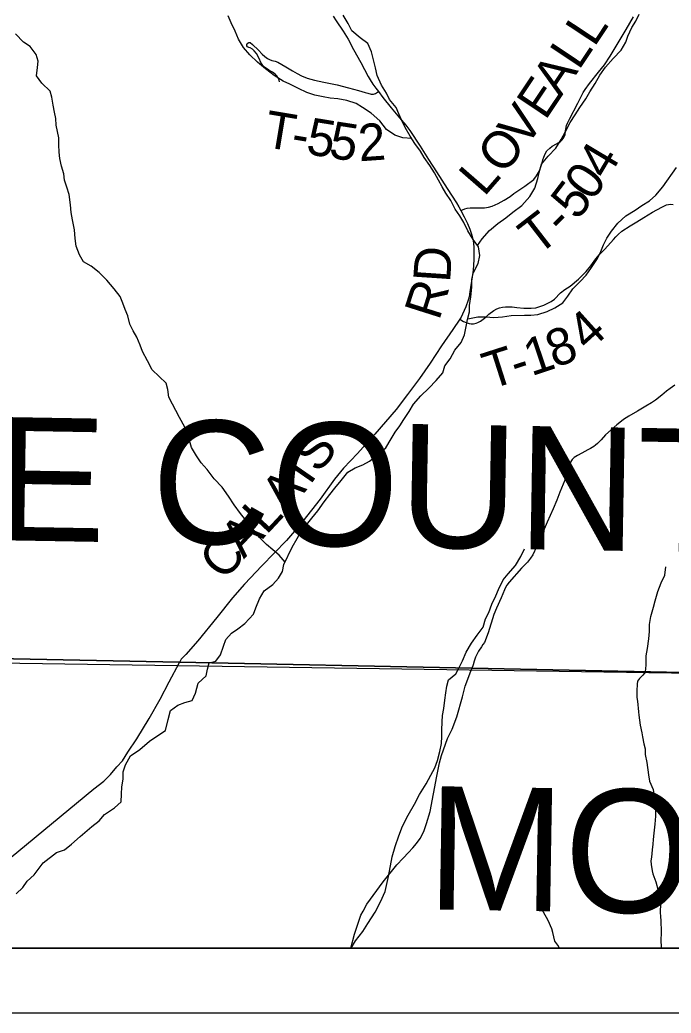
# Model space of a CAD drawing. Extents: x 0 to 34, y 0 to 22.
# Drawn here: x 25.315 to 26.315, y 14 to 15.526 of the extents above; entities that cross this region are included whole.
import ezdxf

# ---------------------------------------------------------------- set-up
doc = ezdxf.new("R2010")
doc.units = 0
for name, color, linetype in [('GM_X_Corporation', 7, 'Continuous'), ('GM_X_County', 7, 'Continuous'), ('GM_X_County_Road', 7, 'Continuous'), ('GM_X_County_Road_Text', 7, 'Continuous'), ('GM_X_County_Text', 7, 'Continuous'), ('GM_X_Minor_River', 7, 'Continuous'), ('GM_X_Township_Road', 7, 'Continuous'), ('GM_X_Township_Road_Text', 7, 'Continuous'), ('SH_Data', 7, 'Continuous')]:
    doc.layers.add(name, color=color, linetype=linetype)

msp = doc.modelspace()

# ---------------------------------------------------------------- linework, layer by layer
at = {"layer": 'GM_X_Corporation'}
msp.add_lwpolyline([(23.5167, 20.3276), (23.5167, 14.5642), (23.7464, 14.562), (24.4108, 14.5557), (24.414, 14.5556), (24.9788, 14.5503), (25.0494, 14.5496), (25.56, 14.5392), (26.009, 14.53), (26.3333, 14.5233), (26.7998, 14.5186), (27.0057, 14.5136), (27.0124, 14.988), (27.0234, 16.6611), (27.0349, 17.5522)], dxfattribs=at)
msp.add_lwpolyline([(23.5167, 20.3276), (23.5167, 14.5642), (23.7464, 14.562), (24.4108, 14.5557), (24.414, 14.5556), (24.9788, 14.5503), (25.0494, 14.5496), (25.56, 14.5392), (26.009, 14.53), (26.3333, 14.5233), (26.7998, 14.5186), (27.0057, 14.5136), (27.0124, 14.988), (27.0234, 16.6611), (27.0349, 17.5522)], dxfattribs=at)
for points in [[(23.5167, 14.5642), (23.5167, 14.1), (30.3167, 14.1), (30.3167, 14.4639), (30.3098, 14.464), (29.2367, 14.4822), (29.1713, 14.4832), (28.7853, 14.4893), (28.4032, 14.497), (27.8031, 14.5091), (27.2999, 14.5107), (27.0057, 14.5136), (26.7998, 14.5186), (26.3333, 14.5233), (26.009, 14.53), (25.56, 14.5392), (25.0494, 14.5496), (24.9788, 14.5503), (24.414, 14.5556), (24.4108, 14.5557), (23.7464, 14.562)], [(23.5167, 14.5642), (23.5167, 14.1), (27.795, 14.1), (27.8031, 14.5091), (27.2999, 14.5107), (27.0057, 14.5136), (26.7998, 14.5186), (26.3333, 14.5233), (26.009, 14.53), (25.56, 14.5392), (25.0494, 14.5496), (24.9788, 14.5503), (24.414, 14.5556), (24.4108, 14.5557), (23.7464, 14.562)]]:
    msp.add_lwpolyline(points, close=True, dxfattribs=at)
at = {"layer": 'GM_X_County'}
msp.add_line((23.5167, 14.5642), (30.3167, 14.4639), dxfattribs=at)
at = {"layer": 'GM_X_County_Road'}
for points in [[(25.7962, 15.5317), (25.801, 15.5244), (25.8113, 15.5087), (25.819, 15.4965), (25.8276, 15.4806), (25.8387, 15.4604), (25.8498, 15.4392), (25.8529, 15.4338), (25.857, 15.4273), (25.8615, 15.4212), (25.8656, 15.4158), (25.8726, 15.4068), (25.8854, 15.3909), (25.8981, 15.3755), (25.9076, 15.3642), (25.9138, 15.3559), (25.9296, 15.332), (25.9427, 15.3115), (25.9547, 15.2928), (25.9715, 15.267), (25.9857, 15.2452), (25.9895, 15.2389), (25.9925, 15.2332), (25.9975, 15.2235), (26.0024, 15.2134), (26.0061, 15.2044), (26.0089, 15.1968), (26.0108, 15.1893), (26.0116, 15.1835), (26.0124, 15.1756), (26.0123, 15.1576), (26.0113, 15.1416), (26.0098, 15.1315), (26.0064, 15.1084), (26.005, 15.1006), (26.0038, 15.0954), (26, 15.0851), (25.9948, 15.0737), (25.9926, 15.0694), (25.9908, 15.0663), (25.9798, 15.0502), (25.9626, 15.0255), (25.9451, 14.9988), (25.9286, 14.975), (25.9106, 14.9503), (25.893, 14.9275), (25.8603, 14.8896), (25.8336, 14.86), (25.8119, 14.8371), (25.7981, 14.8206), (25.7763, 14.7897), (25.7498, 14.756), (25.7401, 14.744), (25.7245, 14.7262), (25.6868, 14.6873), (25.66, 14.6589), (25.6414, 14.6379), (25.6172, 14.6077), (25.5882, 14.572), (25.5699, 14.5508), (25.5624, 14.5439), (25.5602, 14.5386)], [(25.2092, 14.1), (25.2296, 14.1618), (25.2313, 14.1687), (25.2327, 14.1725), (25.2342, 14.1752), (25.2363, 14.1795), (25.2381, 14.1826), (25.2403, 14.1864), (25.2443, 14.1911), (25.2476, 14.1954), (25.4286, 14.3447), (25.4438, 14.3563), (25.4541, 14.3664), (25.4637, 14.3782), (25.4725, 14.3877), (25.4808, 14.4011), (25.4947, 14.4212), (25.5133, 14.4528), (25.5302, 14.4822), (25.544, 14.509), (25.5602, 14.5386)]]:
    msp.add_lwpolyline(points, dxfattribs=at)
at = {"layer": 'GM_X_Minor_River'}
for points in [[(25.9169, 15.3437), (25.9034, 15.3446), (25.8909, 15.3491), (25.878, 15.3574), (25.8677, 15.371), (25.8548, 15.3827), (25.8415, 15.3914), (25.8316, 15.3978), (25.8172, 15.4024), (25.8035, 15.4046), (25.7917, 15.4057), (25.7807, 15.4079), (25.7682, 15.4105), (25.7557, 15.4147), (25.7428, 15.4207), (25.7298, 15.4271), (25.7192, 15.432), (25.7055, 15.4407), (25.6922, 15.4509), (25.6801, 15.4611), (25.6679, 15.4725), (25.6584, 15.4838), (25.6508, 15.4967), (25.6458, 15.5088), (25.6393, 15.5217), (25.6347, 15.5323)], [(25.968, 14.9944), (25.9759, 15.0051), (25.9831, 15.0184), (25.9929, 15.0302), (25.9978, 15.042), (26.0004, 15.0552), (26.0027, 15.0655), (26.0057, 15.0777), (26.0057, 15.0871), (26.0079, 15.1004), (26.009, 15.1152), (26.009, 15.1278), (26.012, 15.1377), (26.0192, 15.1517), (26.0215, 15.1639), (26.0195, 15.1772), (26.0115, 15.1889), (26.0032, 15.2022), (25.9967, 15.2147), (25.991, 15.2249), (25.9834, 15.2355), (25.9769, 15.2484), (25.9693, 15.2597), (25.9639, 15.2696), (25.9582, 15.2798), (25.9517, 15.2912), (25.9449, 15.3022), (25.9358, 15.3147), (25.9304, 15.3245), (25.9217, 15.3363), (25.9144, 15.3476), (25.9068, 15.3605), (25.9011, 15.3723), (25.8973, 15.3817), (25.8931, 15.3912), (25.8828, 15.4037), (25.8779, 15.4136), (25.8702, 15.4257), (25.8638, 15.4405), (25.8611, 15.4522), (25.858, 15.4647), (25.8553, 15.4769), (25.8496, 15.4898), (25.8378, 15.4985), (25.8249, 15.509), (25.8192, 15.5204), (25.8116, 15.5333)], [(26.0179, 15.1796), (26.0252, 15.1897), (26.0365, 15.2026), (26.049, 15.2133), (26.0616, 15.2221), (26.0722, 15.2305), (26.0858, 15.2411), (26.0983, 15.2545), (26.1062, 15.2674), (26.1104, 15.2822), (26.1126, 15.2917), (26.1164, 15.3042), (26.1266, 15.3168), (26.1383, 15.329), (26.1467, 15.3423), (26.1531, 15.3548), (26.1603, 15.3682), (26.1682, 15.3803), (26.1754, 15.3917), (26.1845, 15.405), (26.1905, 15.4153), (26.1985, 15.4282), (26.206, 15.4412), (26.2147, 15.4533), (26.2265, 15.4667), (26.2389, 15.4796), (26.2458, 15.4918), (26.2488, 15.5013), (26.2552, 15.5146), (26.2612, 15.5241), (26.2661, 15.5347)], [(25.5183, 14.9885), (25.5111, 15.0024), (25.5034, 15.0168), (25.4996, 15.0263), (25.4943, 15.0388), (25.489, 15.0483), (25.484, 15.0585), (25.4806, 15.0714), (25.4767, 15.0809), (25.4729, 15.0908), (25.4687, 15.101), (25.4596, 15.1131), (25.4482, 15.1264), (25.4368, 15.1377), (25.4242, 15.1479), (25.4125, 15.1543), (25.4064, 15.1649), (25.4014, 15.1782), (25.3999, 15.19), (25.3987, 15.2033), (25.3956, 15.2188), (25.3937, 15.2302), (25.3925, 15.2419), (25.3906, 15.2579), (25.3872, 15.2693), (25.3833, 15.2799), (25.3822, 15.2894), (25.3787, 15.3015), (25.3761, 15.3133), (25.3753, 15.3227), (25.3745, 15.3341), (25.3745, 15.3448), (25.3726, 15.3546), (25.3706, 15.3641), (25.3702, 15.3744), (25.3679, 15.3842), (25.366, 15.3948), (25.3637, 15.4074), (25.3614, 15.4168), (25.3485, 15.4286), (25.3405, 15.4403), (25.342, 15.4528), (25.3427, 15.4627), (25.3397, 15.4729), (25.3305, 15.4854), (25.3206, 15.4919), (25.3081, 15.5047)], [(26.0029, 15.0665), (26.0186, 15.0697), (26.0308, 15.0698), (26.0429, 15.069), (26.0562, 15.0698), (26.0698, 15.0718), (26.0903, 15.0726), (26.0998, 15.0726), (26.1104, 15.0734), (26.1252, 15.078), (26.1366, 15.0838), (26.1491, 15.0914), (26.1567, 15.1017), (26.1646, 15.1131), (26.1756, 15.1241), (26.1847, 15.134), (26.1923, 15.1439), (26.2013, 15.158), (26.2066, 15.1675), (26.2115, 15.1804), (26.2164, 15.1907), (26.224, 15.2013), (26.2335, 15.2135), (26.2456, 15.2249), (26.2604, 15.2337), (26.2706, 15.241), (26.282, 15.2478), (26.2918, 15.257), (26.3028, 15.2695), (26.3237, 15.2992)], [(25.7222, 14.6928), (25.7133, 14.7037), (25.7034, 14.712), (25.6939, 14.7199), (25.6828, 14.7309), (25.6744, 14.7422), (25.6657, 14.7528), (25.6538, 14.7675), (25.6443, 14.7811), (25.6355, 14.7943), (25.6256, 14.8079), (25.6134, 14.8207), (25.6027, 14.8355), (25.5932, 14.8456), (25.586, 14.8562), (25.5783, 14.8691), (25.5737, 14.885), (25.5683, 14.9005), (25.5599, 14.9152), (25.5545, 14.9258), (25.5492, 14.9357), (25.5438, 14.9463), (25.5422, 14.958), (25.5395, 14.9679), (25.5183, 14.9885)], [(25.6058, 14.538), (25.6158, 14.5408), (25.6229, 14.5507), (25.6278, 14.564), (25.6315, 14.5739), (25.6398, 14.5838), (25.6496, 14.5903), (25.6605, 14.5987), (25.6737, 14.6128), (25.6774, 14.6227), (25.683, 14.6368), (25.6901, 14.6486), (25.7033, 14.6585), (25.7123, 14.6681), (25.7183, 14.6783), (25.7205, 14.6894), (25.7333, 14.716), (25.7407, 14.7293), (25.7471, 14.7403), (25.7554, 14.7503), (25.7633, 14.7605), (25.7727, 14.772), (25.7824, 14.7857), (25.7911, 14.7971), (25.7986, 14.8066), (25.8084, 14.8185), (25.8185, 14.8314), (25.8298, 14.8379), (25.8419, 14.8426), (25.8521, 14.8479), (25.8668, 14.8598), (25.877, 14.8686), (25.8852, 14.8826), (25.8916, 14.8925), (25.8987, 14.9021), (25.9047, 14.912), (25.913, 14.9242), (25.9197, 14.9356), (25.931, 14.9482), (25.9434, 14.96), (25.9543, 14.9718), (25.9645, 14.9836), (25.968, 14.9944)], [(25.9895, 14.5301), (25.995, 14.5415), (26.0006, 14.5548), (26.0089, 14.5682), (26.0172, 14.5807), (26.0265, 14.5929), (26.0303, 14.6058), (26.0351, 14.6157), (26.04, 14.6283), (26.0463, 14.6412), (26.0501, 14.6511), (26.0575, 14.6655), (26.0651, 14.6751), (26.0763, 14.688), (26.0846, 14.7014), (26.0902, 14.7132)], [(26.2761, 14.5242), (26.2771, 14.5348), (26.277, 14.5492), (26.2792, 14.5603), (26.2814, 14.5751), (26.2824, 14.5865), (26.2824, 14.5971), (26.2842, 14.6096), (26.2883, 14.624), (26.2909, 14.6335), (26.295, 14.648), (26.3002, 14.6609), (26.3058, 14.6727), (26.3072, 14.6856)], [(25.3091, 14.1831), (25.3192, 14.1931), (25.3262, 14.203), (25.3367, 14.2127), (25.3504, 14.2311), (25.371, 14.247), (25.3834, 14.251), (25.3943, 14.2595), (25.4077, 14.2714), (25.4253, 14.2865), (25.4369, 14.2954), (25.4451, 14.3054), (25.4604, 14.3155), (25.4705, 14.3248), (25.4711, 14.3365), (25.4717, 14.3476), (25.4734, 14.3594), (25.4736, 14.3708), (25.4773, 14.3815), (25.4846, 14.3952), (25.4992, 14.4053), (25.5142, 14.4177), (25.5269, 14.4266), (25.5386, 14.4344), (25.5425, 14.4512), (25.5464, 14.4649), (25.5573, 14.4734), (25.5682, 14.4773), (25.5795, 14.4802), (25.5847, 14.4916), (25.589, 14.5069), (25.6013, 14.5181), (25.603, 14.5284), (25.6058, 14.538)], [(25.8236, 14.1), (25.8305, 14.1113), (25.8417, 14.1255), (25.8494, 14.1378), (25.8609, 14.155), (25.869, 14.1711), (25.876, 14.1868), (25.8813, 14.2097), (25.8866, 14.2401), (25.8912, 14.2558), (25.8971, 14.2722), (25.9029, 14.2871), (25.9114, 14.3043), (25.9213, 14.3212), (25.9287, 14.3357), (25.939, 14.3522), (25.9464, 14.3656), (25.9523, 14.3771), (25.9567, 14.3882), (25.9603, 14.4019), (25.9627, 14.4141), (25.963, 14.4251), (25.9632, 14.435), (25.9638, 14.4475), (25.9644, 14.4574), (25.9661, 14.4681), (25.9678, 14.481), (25.9695, 14.4921), (25.9709, 14.5023), (25.9734, 14.5123), (25.9848, 14.5214), (25.9895, 14.5301)], [(26.2761, 14.5242), (26.272, 14.5194), (26.2668, 14.5142), (26.2637, 14.5102), (26.2634, 14.5053), (26.2628, 14.495), (26.263, 14.4848), (26.2638, 14.4791), (26.2655, 14.4631), (26.266, 14.4578), (26.2677, 14.4423), (26.2702, 14.4309), (26.2714, 14.4245), (26.2735, 14.4139), (26.2755, 14.4059), (26.2756, 14.3972), (26.278, 14.385), (26.2806, 14.3661), (26.2822, 14.3562), (26.2877, 14.3438), (26.2915, 14.3203), (26.2914, 14.3024), (26.2904, 14.2902), (26.2887, 14.2765), (26.2877, 14.2666), (26.2874, 14.2598), (26.2864, 14.2507), (26.2851, 14.2396), (26.2844, 14.2339), (26.2849, 14.2282), (26.2861, 14.2187), (26.2874, 14.2138), (26.2921, 14.2017), (26.2953, 14.1885), (26.2977, 14.1767), (26.299, 14.1684), (26.2988, 14.1547), (26.2993, 14.1486), (26.2998, 14.1418), (26.3, 14.1254), (26.2995, 14.1102), (26.2999, 14.1034), (26.3, 14.1)], [(26.1439, 14.1), (26.1413, 14.1042), (26.1367, 14.1106), (26.1339, 14.1239), (26.1319, 14.1296), (26.1264, 14.1424), (26.1194, 14.1552), (26.1148, 14.1631), (26.1127, 14.173), (26.1119, 14.1787), (26.111, 14.1897), (26.1105, 14.1965), (26.1107, 14.211), (26.1104, 14.2273), (26.1115, 14.2338), (26.1128, 14.2467), (26.1145, 14.2589), (26.1159, 14.2665), (26.1151, 14.2718), (26.1148, 14.287), (26.114, 14.2927), (26.1113, 14.2987)]]:
    msp.add_lwpolyline(points, dxfattribs=at)
at = {"layer": 'GM_X_Township_Road'}
for points in [[(26.1719, 15.398), (26.1803, 15.4143), (26.1834, 15.4193), (26.19, 15.4281), (26.2039, 15.4458), (26.213, 15.4571), (26.2218, 15.4705), (26.2293, 15.4832), (26.2464, 15.5111), (26.2521, 15.5212), (26.2574, 15.5309)], [(25.7137, 15.4307), (25.7131, 15.4336), (25.7116, 15.4366), (25.7095, 15.4402), (25.7072, 15.4426), (25.7031, 15.4455), (25.6974, 15.4489), (25.6924, 15.4522), (25.6892, 15.4546), (25.6869, 15.4573), (25.6851, 15.4605), (25.6823, 15.4669), (25.6782, 15.4745), (25.675, 15.4786), (25.6722, 15.4813), (25.6689, 15.4832), (25.6665, 15.4836), (25.6646, 15.4845), (25.6635, 15.4864), (25.6634, 15.4883), (25.6651, 15.4901), (25.6665, 15.4911), (25.6688, 15.4911), (25.6722, 15.4881), (25.6815, 15.4797), (25.6871, 15.4733), (25.6912, 15.4697), (25.6952, 15.4669), (25.6984, 15.4653), (25.7018, 15.4639), (25.7069, 15.4625), (25.7114, 15.4609), (25.7234, 15.454), (25.7336, 15.4478), (25.7407, 15.4436), (25.7477, 15.4401), (25.7564, 15.4367), (25.7677, 15.4334), (25.782, 15.4303), (25.8024, 15.4261), (25.8197, 15.4215), (25.8351, 15.4175), (25.8453, 15.4144), (25.8496, 15.4133), (25.8544, 15.4119), (25.8583, 15.4118), (25.8613, 15.4129), (25.8656, 15.4158)], [(25.9925, 15.2332), (25.9985, 15.2356), (26.002, 15.2366), (26.0066, 15.2374), (26.0212, 15.2372), (26.0288, 15.2375), (26.0348, 15.2385), (26.0403, 15.2401), (26.0497, 15.2441), (26.0591, 15.249), (26.068, 15.2546), (26.074, 15.2592), (26.0907, 15.2706), (26.1044, 15.2809), (26.1087, 15.2863), (26.113, 15.2941), (26.1166, 15.3048), (26.1185, 15.311), (26.12, 15.3152), (26.1219, 15.3201), (26.1246, 15.3247), (26.1289, 15.3289), (26.1329, 15.3321), (26.1391, 15.3354), (26.1453, 15.3391), (26.148, 15.3417), (26.1507, 15.3452), (26.1524, 15.35), (26.1534, 15.3558), (26.1548, 15.3638), (26.156, 15.3673), (26.1593, 15.3736), (26.1719, 15.398)], [(25.9908, 15.0663), (25.9963, 15.0629), (26.0005, 15.061), (26.0051, 15.0595), (26.0082, 15.0589), (26.0117, 15.059), (26.0157, 15.0599), (26.0186, 15.0609), (26.0225, 15.0632), (26.0267, 15.0662), (26.0313, 15.0698), (26.0355, 15.0738), (26.0429, 15.0795), (26.0476, 15.0823), (26.0517, 15.0837), (26.0561, 15.0849), (26.0612, 15.0853), (26.0664, 15.0854), (26.0713, 15.0852), (26.0782, 15.0843), (26.0893, 15.083), (26.1006, 15.0832), (26.1074, 15.0839), (26.1139, 15.0856), (26.1197, 15.0877), (26.1269, 15.0911), (26.1313, 15.0936), (26.1362, 15.097), (26.1455, 15.1066), (26.1523, 15.1116), (26.1602, 15.1169), (26.1733, 15.1278), (26.1793, 15.1336), (26.185, 15.1395), (26.1923, 15.1482), (26.1997, 15.159), (26.2048, 15.165), (26.2086, 15.1689), (26.2137, 15.1738), (26.2267, 15.1888), (26.2303, 15.1929), (26.2339, 15.1965), (26.2398, 15.2013), (26.2527, 15.2095), (26.2626, 15.2157), (26.2736, 15.2222), (26.287, 15.2306), (26.3014, 15.2383), (26.3083, 15.2417), (26.3114, 15.2424), (26.3147, 15.2428), (26.3186, 15.2424)], [(26.3212, 14.9646), (26.314, 14.9599), (26.3081, 14.9556), (26.3012, 14.9496), (26.2914, 14.942), (26.2852, 14.9377), (26.2765, 14.9325), (26.2637, 14.9251), (26.2505, 14.9174), (26.2422, 14.9119), (26.2366, 14.9077), (26.2319, 14.904), (26.2147, 14.8887), (26.2077, 14.8808), (26.2024, 14.8752), (26.1994, 14.8727), (26.1966, 14.8705), (26.1918, 14.8676), (26.1876, 14.8654), (26.1781, 14.8604), (26.1716, 14.8568), (26.1667, 14.8535), (26.1633, 14.8505), (26.1614, 14.8473), (26.1597, 14.8424), (26.1566, 14.8312), (26.1523, 14.819), (26.1446, 14.8006), (26.1396, 14.7882), (26.1342, 14.775), (26.1248, 14.7542), (26.1132, 14.7268), (26.1086, 14.7166), (26.1027, 14.7044), (26.0992, 14.699), (26.0946, 14.6931), (26.09, 14.6882), (26.0856, 14.6835), (26.0667, 14.6622), (26.0631, 14.6573), (26.0606, 14.6529), (26.0595, 14.6505), (26.0545, 14.6379), (26.0471, 14.6224), (26.0429, 14.6123), (26.0342, 14.5844), (26.0287, 14.5697), (26.0263, 14.5662), (26.0241, 14.5629), (26.0195, 14.5561), (26.0173, 14.5519), (26.0148, 14.5469), (26.0126, 14.5409), (26.0111, 14.5354), (26.0092, 14.5294)], [(25.8231, 14.1), (25.8288, 14.1213), (25.8386, 14.1507), (25.8423, 14.1565), (25.8478, 14.1676), (25.873, 14.2019), (25.8942, 14.2277), (25.9035, 14.2381), (25.9121, 14.247), (25.9184, 14.254), (25.924, 14.2606), (25.9299, 14.2683), (25.9354, 14.279), (25.9394, 14.2912), (25.9452, 14.3096), (25.9556, 14.3641), (25.9598, 14.3847), (25.9626, 14.3958), (25.972, 14.4222), (25.979, 14.4364), (25.9862, 14.4555), (25.9948, 14.486), (25.9991, 14.5025), (26.0092, 14.5294)]]:
    msp.add_lwpolyline(points, dxfattribs=at)
at = {"layer": 'SH_Data'}
for points in [[(23.4167, 21), (30.4167, 21), (30.4167, 14), (23.4167, 14)], [(23.5167, 20.9), (30.3167, 20.9), (30.3167, 14.1), (23.5167, 14.1)]]:
    msp.add_lwpolyline(points, close=True, dxfattribs=at)

# ---------------------------------------------------------------- texts
at = {"layer": 'GM_X_County_Road_Text'}
for s, rotation, p in [('D', 86.1508, (25.9757, 15.1216)), ('R', 72.3871, (25.9588, 15.0628)), ('S', 49.8574, (25.7729, 14.8278)), ('I', 55.3692, (25.7605, 14.8097)), ('A', 49.4204, (25.724, 14.7666)), ('L', 46.9747, (25.6933, 14.7336)), ('A', 46.8601, (25.659, 14.697)), ('C', 48.2611, (25.6282, 14.6625))]:
    msp.add_text(s, height=0.0568, rotation=rotation, dxfattribs=at).set_placement(p)
at = {"layer": 'GM_X_County_Text'}
for s, rotation, p in [('NOBLE COUNTY', 359.0214, (24.5871, 14.7385)), ('MONROE COUNTY', 359.0616, (25.9393, 14.1595))]:
    msp.add_text(s, height=0.189394, rotation=rotation, dxfattribs=at).set_placement(p)
at = {"layer": 'GM_X_Township_Road_Text'}
for s, rotation, p in [('L', 56.5615, (26.1973, 15.483)), ('L', 56.2596, (26.1735, 15.4474)), ('A', 56.2486, (26.1457, 15.4058)), ('E', 56.2393, (26.1221, 15.3705)), ('V', 54.1549, (26.0915, 15.3281)), ('T', 350.5419, (25.6878, 15.3313)), ('5', 350.6632, (25.7529, 15.3204)), ('5', 351.0876, (25.7879, 15.3147)), ('2', 3.9925, (25.8364, 15.3087)), ('O', 50.1389, (26.0568, 15.2863)), ('-', 350.5551, (25.7297, 15.3243)), ('4', 59.1997, (26.2171, 15.2785)), ('L', 48.9092, (26.028, 15.2532)), ('0', 54.3296, (26.1938, 15.2457)), ('5', 52.7148, (26.1716, 15.2164)), ('T', 37.7408, (26.11, 15.1625)), ('-', 44.8667, (26.1494, 15.1936)), ('4', 42.0749, (26.1882, 15.015)), ('8', 21.5809, (26.1369, 14.9905)), ('1', 18.5646, (26.1007, 14.9783)), ('T', 17.76, (26.0372, 14.9579)), ('-', 17.912, (26.0778, 14.9709))]:
    msp.add_text(s, height=0.0568, rotation=rotation, dxfattribs=at).set_placement(p)

doc.saveas('drawing.dxf')
